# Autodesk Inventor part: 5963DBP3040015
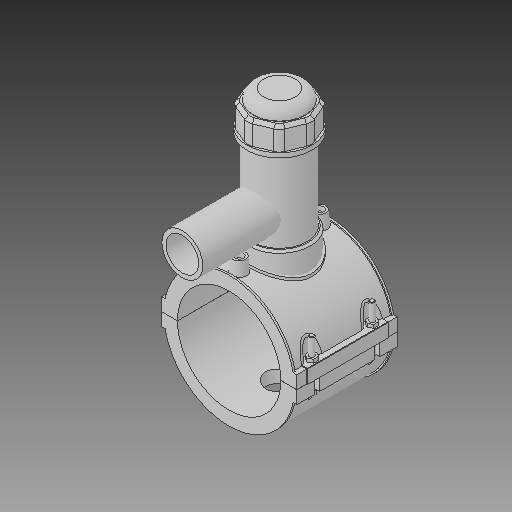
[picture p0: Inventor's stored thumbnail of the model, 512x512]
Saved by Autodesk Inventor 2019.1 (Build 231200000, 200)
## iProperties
Created: 2017-07
Part Number: 5963DBP3040015
Material: Generic
Description: PLASSON TAPPING SADDLE 4''DIPS x 1 1/2''IPS
Document SubType Name: Modeling
Designer: KIM
Density: 1 g/cm^3
Appearance: Default
Author: KIM
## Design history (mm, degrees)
derived "5963DBP_5963BUP.ipt"
feature "Solid1::5963DBP_5963BUP.ipt"
feature "Solid2::5963DBP_5963BUP.ipt"
feature "Solid3::5963DBP_5963BUP.ipt"
tag "TaggingFeature1"
body "Solid1"
body "Solid2"
body "Solid3"
other parameters: "d0" = 121.3, "d2" = 159.004, "d3" = 30.325, "d4" = 118.11, "d5" = 0, "d6" = 0.1, "d8" = 0, "d19" = 6, "d20" = 6, "d21" = 70.866, "d23" = 0, "d24" = 35.433, "d26" = 0, "d27" = 3, "d28" = 3, "d29" = 3, "d30" = 40.43333, "d31" = 6, "d32" = 0, "d33" = 0, "d34" = 0.6, "d40" = 78.21424, "d41" = 76.419, "d43" = 0, "d45" = 0, "d47" = 146.072, "d70" = 15, "d72" = 0, "d73" = 6, "d75" = 5, "d76" = 0, "d77" = 6.065, "d78" = 90.65, "d79" = 15, "d80" = 47.244, "d82" = 5 deg, "d84" = 4, "d85" = 14, "d86" = 0, "d87" = 3, "d88" = 0, "d89" = 1, "d90" = 1, "d91" = 94.488, "d92" = 0, "d93" = 0.5, "d94" = 63.84211, "d96" = 153.42024, "d97" = 2.3622, "d98" = 0, "d120" = 140 deg, "d121" = 24.228, "d122" = 20 deg, "d123" = 300.824, "d124" = 90.2472, "d126" = 0, "d143" = 124.939, "d145" = 22.39385, "d149" = 1.8195, "d150" = 24.63323, "d153" = 118.11, "d154" = 0, "d156" = 75.206, "d157" = 160 deg, "d159" = 5.8224, "d161" = 1.8195, "d162" = 70.866, "d163" = 0, "d164" = 60.65, "d167" = 12.13, "d168" = 73.37171, "d170" = 3.4335, "d172" = 0, "d173" = 1, "d175" = 60.65, "d176" = 20 deg, "d177" = 8.491, "d178" = 29.112, "d180" = 0, "d183" = 11.6448, "d184" = 6.7928, "d185" = 38.38575, "d186" = 38.38575, "d187" = 75.206, "d188" = 8.7336, "d189" = 8.491, "d190" = 0, "d191" = 112.809, "d193" = 7.3248, "d194" = 4.13385, "d195" = 90 deg, "d197" = 0, "d199" = 0, "d200" = 14.556, "d202" = 0, "d203" = 177.038, "d204" = 72.59805, "d205" = 53.4933, "d206" = 64.95615, "d207" = 132.7785, "d208" = 138.08964, "d209" = 164.64534, "d210" = 65.72034, "d211" = 76.419, "d212" = 61.1352, "d213" = 36.8766, "d216" = 0, "d217" = 12.13, "d218" = 12.13, "d219" = 2.426, "d222" = 121.3, "d224" = 0, "d225" = 65.024, "d226" = 48.1, "d227" = 38.48, "d228" = 114.046, "d230" = 3.639, "d_" = 121.3, "B_" = 159.004, "L_" = 118.11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
